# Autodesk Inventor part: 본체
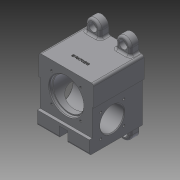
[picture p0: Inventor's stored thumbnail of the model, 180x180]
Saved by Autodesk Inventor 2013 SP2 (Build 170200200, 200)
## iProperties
Created: 2024-11
Part Number: 본체
Material: 알루미늄 6061
Document SubType Name: Modeling
Designer: a
Density: 2.71 g/cm^3
Author: a
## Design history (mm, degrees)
sketch "스케치1"
  geometry: L1 (-38, -42.5)-(38, -42.5); L2 (38, -42.5)-(38, 42.5); L3 (38, 42.5)-(-38, 42.5); L4 (-38, 42.5)-(-38, -42.5); L5 (-38, -42.5)-(38, 42.5); L6 (38, -42.5)-(-38, 42.5); 1 further point
  constraints: 12 end point, 2 midpoint, 2 parallel, 1 horizontal, 1 perpendicular
  dimensions: "d0" = 76 distance of L3.end L2.end; "d1" = 85 distance of L2.end L1.end
extrude "돌출1" new body sketch "스케치1" distance "d2" = 74; taper "d3" = 0 deg
sketch "스케치2"
  geometry: L1 (-38, -42.5)-(-36, -42.5); L2 (-36, -42.5)-(-36, 13.5); L3 (-36, 13.5)-(-38, 13.5); L4 (-38, 13.5)-(-38, -42.5); L5 (38, -42.5)-(36, -42.5); L6 (36, -42.5)-(36, 13.5); L7 (36, 13.5)-(38, 13.5); L8 (38, 13.5)-(38, -42.5); 1 further point
  constraints: 16 end point, 4 parallel, 2 horizontal, 2 perpendicular
  dimensions: "d4" = 2 distance of L2.end L3.end; "d6" = 2 distance of L6.end L7.end (= d4); "d7" = 56 distance of L5.end L6.end; "d8" = 56 distance of L1.end L2.end (= d7)
extrude "돌출2" cut sketch "스케치2" stored distance "d9" = 74; taper "d10" = 0 deg
sketch "스케치3"
  geometry: L1 (-36, -42.5)-(36, -42.5) reference; L2 (-6, -42.5)-(6, -42.5); L3 (6, -42.5)-(6, -27.5); L4 (6, -27.5)-(-6, -27.5); L5 (-6, -27.5)-(-6, -42.5); L6 (0, -27.5)-(0, 0)
  constraints: 10 end point, 2 parallel, 1 horizontal, 1 midpoint, 1 perpendicular, 1 point on line, 1 vertical
  dimensions: "d11" = 12 distance of L3.end L4.end; "d13" = 15 distance of L2.end L3.end
extrude "돌출3" cut sketch "스케치3" stored distance "d14" = 74; taper "d15" = 0 deg
sketch "스케치4"
  geometry: L1 (0, 85)-(-4, 85); L2 (-4, 85)-(-4, 19); L3 (-4, 19)-(0, 19); L4 (0, 19)-(0, 85); L5 (-74, 85)-(0, 85) reference; L6 (0, 56)-(0, 85) reference; 1 further point
  constraints: 8 end point, 2 collinear, 2 parallel, 1 horizontal, 1 perpendicular
  dimensions: "d16" = 4 distance between parallel lines of L2 L4; "d18" = 66 distance between parallel lines of L3 L1
extrude "돌출4" cut sketch "스케치4" stored distance "d19" = 74; taper "d20" = 0 deg
sketch "스케치5"
  geometry: L1 (-38, 42.5)-(38, 42.5) reference; L2 (-6, -27.5)-(6, -27.5) reference; L3 (-31, 42.5)-(-31, 52.5); L4 (-11, 42.5)-(-11, 52.5); A1 r 10 centre (-21, 52.5) between (-11, 52.5) and (-31, 52.5); 1 further point
  constraints: 4 end point, 2 point on circle, 2 point on line, 2 tangent, 1 centre point, 1 parallel, 1 perpendicular
  dimensions: "d21" = 21 horizontal distance of point (0, 0) A1.centre; "d22" = 20 distance between parallel lines of L4 L3; "d23" = 10 distance of L3.start L3.end
extrude "돌출5" join sketch "스케치5" distance "d24" = 12; taper "d25" = 0 deg
sketch "스케치6"
  geometry: A1 r 10 centre (21, 52.5) between (31, 52.5) and (11, 52.5) reference; 2 further points
  constraints: 1 coincident
hole "구멍1" sketch "스케치6" at (21, 52.5) diameter "d26" = 6.6; stored, may be unused: countersink angle "d30" = 90 deg, drill point angle "d32" = 118 deg; dims "d27" = 6, "d28" = 11, "d29" = 6.6, "d31" = 8
node "작업 평면1"
sketch "스케치7"
  geometry: L1 (-2, 66)-(74, 66) reference; L2 (72, 0)-(0, 0) reference; L3 (36, 23.5)-(36, 33); C1 r 23.5 at (36, 33)
  constraints: 2 end point, 1 centre point, 1 perpendicular
  dimensions: "d33" = 47 diameter of C1; "d34" = 33 distance from line of L3.end L1
extrude "돌출6" cut sketch "스케치7" distance "d35" = 4; taper "d36" = 0 deg
sketch "스케치8"
  geometry: C1 r 23.5 at (0, 0) reference; C2 r 22 at (0, 0); 1 further point
  constraints: 1 centre point, 1 coincident
  dimensions: "d37" = 44 diameter of C2
extrude "돌출7" cut sketch "스케치8" distance "d38" = 48; taper "d39" = 0 deg
sketch "스케치9"
  geometry: C1 r 22 at (0, 0) reference; C2 r 17.5 at (0, 0); 1 further point
  constraints: 1 centre point, 1 coincident
  dimensions: "d40" = 35 diameter of C2
extrude "돌출8" cut sketch "스케치9" distance "d41" = 11; taper "d42" = 0 deg
sketch "스케치10"
  geometry: C1 r 17.5 at (0, 0) reference; C2 r 15 at (0, 0); 1 further point
  constraints: 1 centre point, 1 coincident
  dimensions: "d43" = 30 diameter of C2
extrude "돌출9" cut sketch "스케치10" distance "d44" = 3; taper "d45" = 0 deg
chamfer "모따기1" distance "d46" = 1; stored, may be unused: second distance "d47" = 2, angle "d48" = 45 deg
fillet "모깎기1" dims "d49" = 3
chamfer "모따기2" distance "d50" = 1; stored, may be unused: second distance "d51" = 2, angle "d52" = 45 deg
fillet "모깎기2" dims "d53" = 0.6
fillet "모깎기3" dims "d54" = 3
sketch "스케치11"
  geometry: L1 (72, 0)-(0, 0) reference; L2 (36, 33)-(36, 61.5); L3 (36, 33)-(56.153, 53.153); C1 r 24.5 at (36, 33) reference; A1 r 28.5 centre (36, 33) between (36, 61.5) and (56.153, 53.153); 2 further points
  constraints: 4 end point, 2 coincident, 2 point on circle, 1 centre point, 1 perpendicular
  dimensions: "d55" = 57 diameter of A1; "d56" = 45 deg angle of L3 L2
hole "구멍2" sketch "스케치11" at (56.153, 53.153) diameter "d58" = 3.242; stored, may be unused: countersink angle "d62" = 90 deg, drill point angle "d64" = 118 deg; dims "d59" = 8, "d60" = 11, "d61" = 6.6, "d63" = 10
sketch "스케치12"
  geometry: L1 (-62.5, 0)-(-52.5, 0) reference; L2 (42.5, 0)-(42.5, 70) reference; C1 r 16.5 at (-14.5, 42); 1 further point
  constraints: 1 centre point
  dimensions: "d68" = 33 diameter of C1; "d69" = 42 distance from line of L1 C1.centre; "d70" = 57 distance from line of L2 C1.centre
extrude "돌출10" cut sketch "스케치12" stored distance "d71" = 3; taper "d72" = 0 deg
sketch "스케치13"
  geometry: L1 (-58, 12)-(-26, 12); L2 (-26, 12)-(-26, 44); L3 (-26, 44)-(-58, 44); L4 (-58, 44)-(-58, 12); L5 (-58, 12)-(-26, 44); L6 (-26, 12)-(-58, 44); C1 r 16.5 at (-42, 28) reference; 5 further points
  constraints: 12 end point, 4 coincident, 2 midpoint, 2 parallel, 1 horizontal, 1 perpendicular
  dimensions: "d73" = 32 distance of L1.start L1.end; "d75" = 32 distance of L1.end L2.end
hole "구멍3" sketch "스케치13" at (-58, 44), (-26, 44), (-26, 12), (-58, 12) diameter "d76" = 3.242; stored, may be unused: countersink angle "d80" = 90 deg, drill point angle "d82" = 118 deg; dims "d77" = 8, "d78" = 11, "d79" = 6.6, "d81" = 10
node "작업 평면2"
sketch "스케치14"
  geometry: L1 (0, 74)-(12, 74) reference; L2 (6, 74)-(6, 62); L3 (6, 62)-(6, 22); 2 further points
  constraints: 4 end point, 2 coincident, 1 collinear, 1 midpoint, 1 perpendicular
  dimensions: "d83" = 12 distance of L2.start L2.end; "d84" = 40 distance of L3.start L3.end
hole "구멍4" sketch "스케치14" at (6, 62), (6, 22) diameter "d85" = 3.242; stored, may be unused: countersink angle "d89" = 90 deg, drill point angle "d91" = 118 deg; dims "d86" = 8, "d87" = 11, "d88" = 6.6, "d90" = 10
sketch "스케치15"
  geometry: L1 (0, 0)-(76, 0) reference; L2 (38, 20)-(38, 0); 1 further point
  constraints: 2 end point, 1 midpoint, 1 vertical, 1 other
  dimensions: "d92" = 20 distance from line of L1 L2.start
feature "엠보싱1" sketch "스케치15" dims "d93" = 0.5, "d94" = 0
fillet "모깎기4" dims "d95" = 3
fillet "모깎기5" dims "d96" = 3
fillet "모깎기6" dims "d97" = 3
chamfer "모따기3" distance "d98" = 1; stored, may be unused: second distance "d99" = 2, angle "d100" = 45 deg
fillet "모깎기7" dims "d101" = 3
chamfer "모따기4" distance "d102" = 1; stored, may be unused: second distance "d103" = 2, angle "d104" = 45 deg
node "솔리드1"
mirror "대칭1"
mirror "대칭2"
pattern_circular "원형 패턴1" dims angle "d66" = 360 deg
mirror "대칭3"
